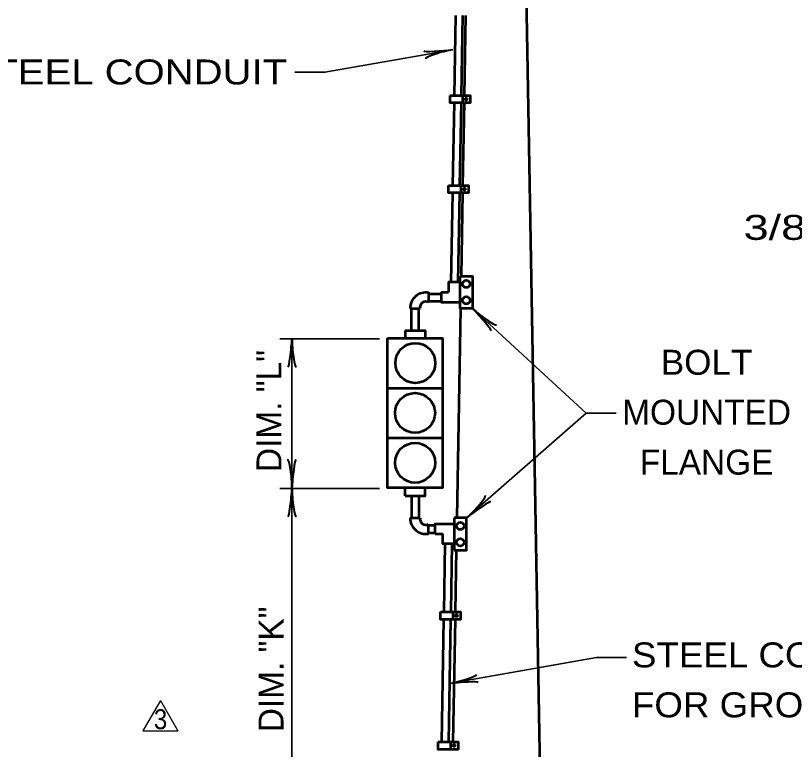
# Model space of a CAD drawing. Extents: x 12366 to 13046, y 9129 to 9570.
# Drawn here: x 12606.9 to 12684.9, y 9408.1 to 9481.6 of the extents above; entities that cross this region are included whole.
import ezdxf
from ezdxf.enums import TextEntityAlignment as Align

# ---------------------------------------------------------------- set-up
doc = ezdxf.new("R2010")
doc.units = 0
doc.layers.add('1', color=7, linetype='Continuous', lineweight=53)

msp = doc.modelspace()

# ---------------------------------------------------------------- linework, layer by layer
at = {"layer": '1'}
for p, q in [((12657.031, 9542.164), (12659.562, 9397.186)), ((12650.972, 9481.589), (12650.833, 9473.6)), ((12651.672, 9481.593), (12651.533, 9473.598)), ((12651.974, 9481.593), (12651.835, 9473.598)), ((12651.68, 9473.599), (12651.68, 9472.849)), ((12650.82, 9472.845), (12650.676, 9464.594)), ((12651.52, 9472.845), (12651.376, 9464.601)), ((12651.822, 9472.847), (12651.677, 9464.597)), ((12651.513, 9464.596), (12651.513, 9463.846)), ((12650.663, 9463.846), (12650.506, 9454.892)), ((12651.363, 9463.842), (12651.206, 9454.892)), ((12651.664, 9463.839), (12651.519, 9455.519)), ((12651.42, 9452.269), (12651.42, 9455.519)), ((12648.277, 9453.746), (12649.497, 9453.746)), ((12648.278, 9453.892), (12648.278, 9452.892)), ((12649.528, 9453.892), (12650.278, 9453.892)), ((12648.277, 9453.003), (12649.513, 9453.003)), ((12646.42, 9452.269), (12647.42, 9452.269)), ((12646.552, 9450.054), (12646.552, 9452.274)), ((12647.296, 9450.054), (12647.296, 9452.29)), ((12651.462, 9452.269), (12651.097, 9431.32)), ((12645.924, 9450.054), (12645.924, 9449.304)), ((12644.174, 9444.304), (12649.674, 9444.304)), ((12649.674, 9439.304), (12644.174, 9439.304)), ((12645.924, 9433.523), (12645.924, 9434.273)), ((12646.552, 9433.523), (12646.552, 9431.303)), ((12647.296, 9433.523), (12647.296, 9431.287)), ((12646.42, 9431.309), (12647.42, 9431.309)), ((12650.825, 9431.324), (12650.825, 9428.074)), ((12652.075, 9431.324), (12650.825, 9431.324)), ((12648.278, 9429.727), (12648.278, 9430.686)), ((12648.278, 9430.574), (12648.933, 9430.574)), ((12648.278, 9429.83), (12648.933, 9429.83)), ((12648.933, 9429.701), (12649.683, 9429.701)), ((12649.908, 9428.708), (12649.789, 9421.895)), ((12650.608, 9428.708), (12650.489, 9421.895)), ((12651.04, 9428.062), (12650.932, 9421.895)), ((12650.705, 9421.895), (12650.705, 9421.145)), ((12649.776, 9421.136), (12649.562, 9408.881)), ((12650.476, 9421.137), (12650.262, 9408.881)), ((12650.919, 9421.137), (12650.705, 9408.889)), ((12650.481, 9408.882), (12650.481, 9408.132))]:
    msp.add_line(p, q, dxfattribs=at)
at = {"layer": '1', "lineweight": 35}
for p, q in [((12652.67, 9452.269), (12664.058, 9441.804)), ((12643.366, 9449.244), (12633.366, 9449.244)), ((12643.366, 9434.244), (12633.366, 9434.244))]:
    msp.add_line(p, q, dxfattribs=at)
at = {"layer": '1', "lineweight": 25}
for p, q in [((12621.42, 9413.034), (12619.67, 9410.003)), ((12621.42, 9413.034), (12623.17, 9410.003)), ((12619.67, 9410.003), (12623.17, 9410.003))]:
    msp.add_line(p, q, dxfattribs=at)
at = {"layer": '1', "lineweight": 35}
for points in [[(12650.689, 9478.18), (12637.886, 9475.922), (12634.886, 9475.922)], [(12634.59, 9449.28), (12634.59, 9434.28), (12634.59, 9397.186)], [(12652.075, 9431.324), (12664.058, 9441.804), (12667.058, 9441.804)], [(12650.327, 9414.72), (12665.099, 9417.325), (12668.099, 9417.325)]]:
    msp.add_lwpolyline(points, dxfattribs=at)
at = {"layer": '1'}
for points in [[(12650.43, 9473.599), (12652.43, 9473.599), (12652.43, 9472.849), (12650.43, 9472.849)], [(12650.263, 9464.596), (12652.263, 9464.596), (12652.263, 9463.846), (12650.263, 9463.846)], [(12644.174, 9449.304), (12649.674, 9449.304), (12649.674, 9434.304), (12644.174, 9434.304)], [(12649.455, 9421.895), (12651.455, 9421.895), (12651.455, 9421.145), (12649.455, 9421.145)], [(12649.231, 9408.882), (12651.231, 9408.882), (12651.231, 9408.132), (12649.231, 9408.132)]]:
    msp.add_lwpolyline(points, close=True, dxfattribs=at)
for points in [[(12651.42, 9455.519), (12652.67, 9455.519), (12652.67, 9452.269)], [(12651.416, 9454.892), (12650.278, 9454.892), (12650.278, 9453.892)], [(12649.528, 9453.892), (12649.528, 9452.892), (12651.413, 9452.892)], [(12652.67, 9452.269), (12651.502, 9452.269), (12651.42, 9452.269)], [(12645.924, 9450.054), (12647.924, 9450.054), (12647.924, 9449.304)], [(12645.924, 9433.523), (12647.924, 9433.523), (12647.924, 9434.273)], [(12650.825, 9428.074), (12652.075, 9428.074), (12652.075, 9431.324)], [(12648.933, 9429.701), (12648.933, 9430.701), (12650.818, 9430.701)], [(12650.821, 9428.701), (12649.683, 9428.701), (12649.683, 9429.701)]]:
    msp.add_lwpolyline(points, dxfattribs=at)
for centre, radius in [((12652.044, 9473.227), 0.1), ((12651.877, 9464.224), 0.1), ((12652.048, 9454.728), 0.37), ((12652.048, 9453.092), 0.37), ((12646.945, 9446.81), 2), ((12646.915, 9441.819), 2), ((12646.923, 9436.828), 2), ((12651.453, 9430.501), 0.37), ((12651.453, 9428.864), 0.37), ((12651.069, 9421.523), 0.1), ((12650.844, 9408.511), 0.1)]:
    msp.add_circle(centre, radius, dxfattribs=at)
for centre, radius, start, end in [((12648.008, 9452.286), 1.588, 80.22862, 180.62498), ((12647.99, 9452.386), 0.582, 60.40406, 191.58246), ((12648.008, 9431.292), 1.588, 179.69885, 279.77138), ((12647.99, 9431.192), 0.582, 168.41754, 299.59594)]:
    msp.add_arc(centre, radius, start, end, dxfattribs=at)
at = {"layer": '1', "lineweight": 40}
for centre, major_axis, ratio, start_param, end_param in [((12649.548, 9478.194), (1.76, 0.132), 0.07063, 3.140715, 5.41811), ((12649.662, 9477.718), (1.731, 0.464), 0.122415, 0.896353, 3.141593), ((12653.352, 9451.355), (-1.174, 1.318), 0.07063, 3.140715, 5.41811), ((12653.661, 9451.734), (-1.421, 1.093), 0.122415, 0.896353, 3.141593), ((12634.379, 9448.159), (-0.176, -1.756), 0.07063, 6.282307, 8.559703), ((12634.866, 9448.188), (-0.156, 1.786), 0.122415, 0.896353, 3.141593), ((12634.314, 9435.371), (0.156, -1.786), 0.122415, 0.896353, 3.141593), ((12634.802, 9435.4), (0.176, 1.756), 0.07063, 6.282307, 8.559703), ((12634.379, 9433.159), (-0.176, -1.756), 0.07063, 6.282307, 8.559703), ((12634.866, 9433.188), (-0.156, 1.786), 0.122415, 0.896353, 3.141593), ((12652.715, 9432.25), (-1.241, -1.293), 0.122415, 0.896353, 3.141593), ((12653.058, 9431.902), (1.438, 1.024), 0.07063, 6.282307, 8.559703), ((12651.354, 9415.182), (-1.731, -0.464), 0.122415, 0.896353, 3.141593), ((12651.467, 9414.707), (1.76, 0.132), 0.07063, 6.282307, 8.559703)]:
    msp.add_ellipse(centre, major_axis=major_axis, ratio=ratio, start_param=start_param, end_param=end_param, dxfattribs=at)

# ---------------------------------------------------------------- texts
at = {"layer": '1'}
for s, width, p in [('1 1/4" STEEL CONDUIT', 1.2, (12634.109, 9474.7)), ('3/8" X 2 1/2" LAG SCREW', 1.35, (12733.184, 9459.141))]:
    msp.add_text(s, height=2.5, dxfattribs=dict(at, width=width)).set_placement(p, align=Align.RIGHT)
for s, p in [('DIM. "L"', (12633.536, 9442.01)), ('DIM. "K"', (12633.748, 9416.146))]:
    msp.add_text(s, height=2.5, rotation=90, dxfattribs=at).set_placement(p, align=Align.CENTER)
at = {"layer": '1', "width": 1.05}
msp.add_text('BOLT', height=2.5, dxfattribs=at).set_placement((12676.112, 9445.639), align=Align.CENTER)
at = {"layer": '1'}
for s, p in [('MOUNTED', (12676.112, 9440.639)), ('FLANGE', (12676.112, 9435.639))]:
    msp.add_text(s, height=2.5, dxfattribs=at).set_placement(p, align=Align.CENTER)
for s, height, width, p in [('STEEL CONDUIT', 2.5, 1.1, (12668.635, 9416.343)), ('FOR GROUND WIRE', 2.5, 1.1, (12668.635, 9411.343)), ('3', 2, 0.9, (12620.763, 9410.154))]:
    msp.add_text(s, height=height, dxfattribs=dict(at, width=width)).set_placement(p)

doc.saveas('drawing.dxf')
